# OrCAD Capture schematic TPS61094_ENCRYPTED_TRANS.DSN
size B
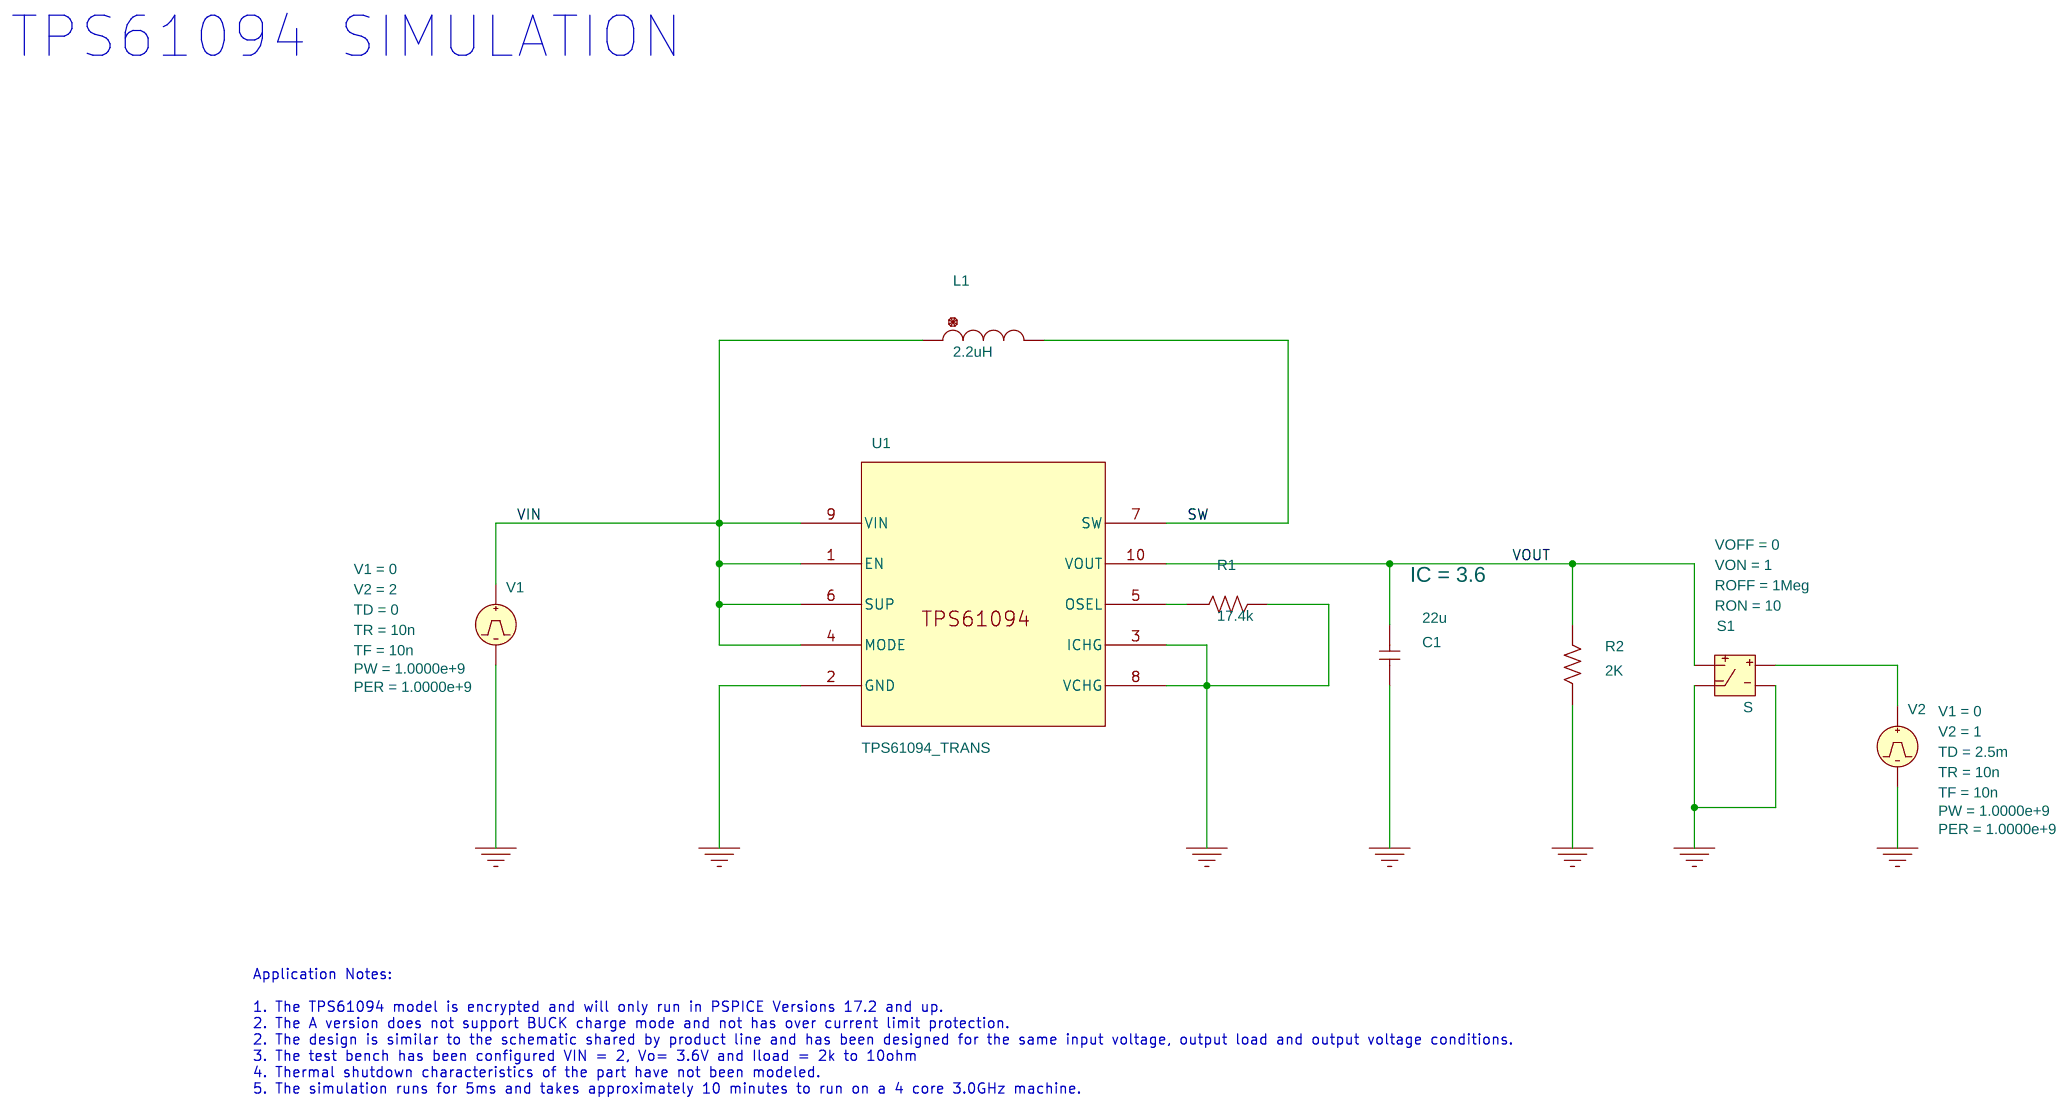
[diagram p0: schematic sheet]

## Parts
C1  22u  [cap196]
L1  2.2uH  [DISC350x175LS200x100034]
R1  17.4k  [AXRC05]
R2  2K  [AXRC05]
S1  S
U1  TPS61094_TRANS
V1  VPULSE
V2  VPULSE

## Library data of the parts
C1 = C: IC: 3.6
L1 = L
R1 R2 = R
S1 = S: ROFF: 1Meg; RON: 10; VOFF: 0; VON: 1
U1 = TPS61094_TRANS_0
V1 = VPULSE: AC: 0; AppProp: Pulse$Voltage$0$-1; DC: 0; PER: 1.0000e+9; PW: 1.0000e+9; TD: 0; TF: 10n; TR: 10n; V1: 0; V2: 2
V2 = VPULSE: AC: 0; AppProp: Pulse$Voltage$0$-1; DC: 0; PER: 1.0000e+9; PW: 1.0000e+9; TD: 2.5m; TF: 10n; TR: 10n; V1: 0; V2: 1

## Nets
VIN: L1.1 U1.1(EN) U1.4(MODE) U1.6(SUP) U1.9(VIN) V1.1(+)
0: C1.2 R1.2 R2.1 S1.1(2) S1.3(4) U1.2(GND) U1.3(ICHG) U1.8(VCHG) V1.2(-) V2.2(-)
SW: L1.2 U1.7(SW)
VOUT: C1.1 R2.2 S1.2(3) U1.10(VOUT)
N01216: R1.1 U1.5(OSEL)
N02490: S1.0(1) V2.1(+)

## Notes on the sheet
- TPS61094 SIMULATION
- Application Notes:
  1. The TPS61094 model is encrypted and will only run in PSPICE Versions 17.2 and up.
  2. The A version does not support BUCK charge mode and not has over current limit protection.
  2. The design is similar to the schematic shared by product line and has been designed for the same input voltage, output load and output voltage conditions.
  3. The test bench has been configured VIN = 2, Vo= 3.6V and Iload = 2k to 10ohm
  4. Thermal shutdown characteristics of the part have not been modeled.
  5. The simulation runs for 5ms and takes approximately 10 minutes to run on a 4 core 3.0GHz machine.
